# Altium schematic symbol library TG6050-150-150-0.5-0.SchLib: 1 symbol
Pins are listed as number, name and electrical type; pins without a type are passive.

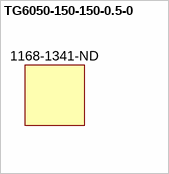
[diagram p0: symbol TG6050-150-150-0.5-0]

## TG6050-150-150-0.5-0
designator H?  Supplier Part Number: 1168-1341-ND
TG SERIES SHEET 150X150X0.5MM; Manufacturer: t-Global Technology; SymbolVersion: use current date i.e. 2008-05-20; SymbolCreator: a0412036; CompType: Used in some BOM reports.  Useful for finding later.; U/M: EA, IN, or GM; Shape: Square; Adhesive: Tacky - Both Sides; Thermal Conductivity: 6.0 W/m-K; Outline: 150.00mm x 150.00mm
footprint TG6050-150-150-0.5-0 (IGLOBAL TECHNOLOGY TG SERIES SHEET 150X150X0.5MM)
